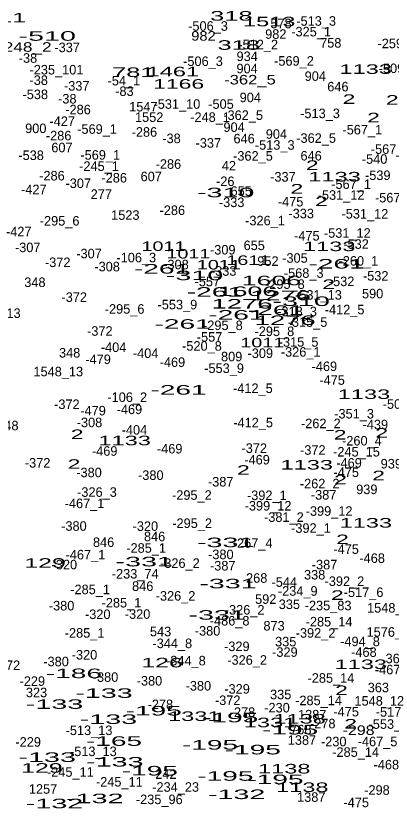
# Model space of a CAD drawing. Extents: x -660434 to -656144, y -997850 to -994016.
# Drawn here: x -658728 to -658570.5, y -995899.8 to -995568.7 of the extents above; entities that cross this region are included whole.
import ezdxf
from ezdxf.enums import TextEntityAlignment as Align

# ---------------------------------------------------------------- set-up
doc = ezdxf.new("R2010")
doc.units = 0
doc.header["$LTSCALE"] = 1.6
doc.layers.add('24', color=7, linetype='Continuous')

msp = doc.modelspace()

# ---------------------------------------------------------------- texts
at = {"layer": '24'}
for s, width, p in [('-411', 1.95, (-658734.082, -995571.44)), ('318', 2, (-658637.537, -995570.7)), ('1513', 1.85, (-658621.664, -995573.09)), ('-510', 2.25, (-658714.797, -995579.13)), ('982', 1.15, (-658649.24, -995579.1)), ('-248_2', 1.35, (-658724.21, -995583.75)), ('318', 2, (-658634.427, -995582.92)), ('781', 2, (-658678.693, -995594.33)), ('1461', 1.85, (-658662.085, -995594.07)), ('1133', 1.85, (-658581.164, -995593.02)), ('-362_5', 1.3, (-658629.73, -995597.47)), ('1166', 1.8, (-658659.663, -995599.24)), ('2', 1.8, (-658588.191, -995605.61)), ('2', 1.8, (-658570.021, -995605.94)), ('2', 1.8, (-658577.881, -995613.36)), ('2', 1.8, (-658603.611, -995633.34)), ('1133', 1.85, (-658594.214, -995638.16)), ('-310', 2.25, (-658639.927, -995644.8)), ('2', 1.8, (-658610.041, -995643.23)), ('2', 1.8, (-658599.771, -995648.51)), ('1011', 1.55, (-658666.026, -995667.31)), ('1133', 1.85, (-658596.484, -995667.38)), ('1011', 1.55, (-658655.566, -995670.48)), ('1611', 1.55, (-658630.425, -995673.19)), ('-261', 2.2, (-658593.385, -995674.69)), ('-261', 2.2, (-658666.635, -995676.8)), ('1011', 1.55, (-658642.796, -995675.09)), ('-310', 2.25, (-658652.977, -995679.57)), ('1606', 2.1, (-658620.713, -995681.72)), ('2', 1.8, (-658596.701, -995683.27)), ('-261', 2.2, (-658644.455, -995686.5)), ('1606', 2.1, (-658630.793, -995686.23)), ('1276', 2.15, (-658616.927, -995688.02)), ('-310', 2.25, (-658608.237, -995690.42)), ('1276', 2.15, (-658633.057, -995691.47)), ('-261', 2.2, (-658618.825, -995694.18)), ('-261', 2.2, (-658635.425, -995696.11)), ('-261', 2.2, (-658657.985, -995699.95)), ('1276', 2.15, (-658614.957, -995698.39)), ('1011', 1.55, (-658624.556, -995707.74)), ('-261', 2.2, (-658659.715, -995727.59)), ('1133', 1.85, (-658581.884, -995729.42)), ('2', 1.8, (-658702.201, -995746.23)), ('2', 1.8, (-658591.891, -995746.42)), ('2', 1.8, (-658574.421, -995745.65)), ('1133', 1.85, (-658682.304, -995748.82)), ('2', 1.8, (-658703.551, -995758.71)), ('1133', 1.85, (-658605.884, -995759)), ('2', 1.8, (-658632.501, -995761.21)), ('2', 1.8, (-658575.761, -995763.51)), ('2', 1.8, (-658591.711, -995765.24)), ('1133', 1.85, (-658581.104, -995783.36)), ('2', 1.8, (-658590.931, -995790.31)), ('-331', 2.25, (-658639.931, -995791.57)), ('129', 1.95, (-658715.713, -995800.22)), ('-331', 2.25, (-658674.111, -995799.64)), ('-331', 2.25, (-658638.971, -995808.86)), ('2', 1.8, (-658593.051, -995813.68)), ('-331', 2.25, (-658643.481, -995822.01)), ('126', 1.95, (-658666.633, -995842.01)), ('1133', 1.85, (-658583.214, -995842.71)), ('-186', 2.2, (-658703.605, -995846.52)), ('2', 1.8, (-658591.321, -995853.63)), ('-133', 2.25, (-658690.991, -995854.79)), ('-133', 2.25, (-658711.731, -995859.4)), ('-195', 2.2, (-658670.115, -995862.19)), ('-133', 2.25, (-658689.121, -995865.74)), ('1331', 1.85, (-658653.094, -995864.48)), ('-195', 2.2, (-658638.035, -995865.07)), ('1138', 1.85, (-658608.914, -995865.57)), ('1331', 1.85, (-658621.294, -995867.12)), ('-195', 2.2, (-658612.885, -995870.16)), ('2', 1.8, (-658587.481, -995867.65)), ('-298', 1.25, (-658584.14, -995870.35)), ('-165', 2.2, (-658686.785, -995874.92)), ('-195', 2.2, (-658646.495, -995876.5)), ('-195', 2.2, (-658628.545, -995878.51)), ('-133', 2.25, (-658714.801, -995881.68)), ('129', 1.95, (-658717.053, -995886.2)), ('-133', 2.25, (-658686.441, -995883.6)), ('1138', 1.85, (-658615.344, -995886.51)), ('-195', 2.2, (-658671.745, -995887.35)), ('-195', 2.2, (-658640.055, -995889.56)), ('-195', 2.2, (-658619.025, -995891)), ('1138', 1.85, (-658607.764, -995894.29)), ('-132', 2.25, (-658694.851, -995898.98)), ('-132', 2.25, (-658635.331, -995897.25)), ('-132', 2.25, (-658711.741, -995901.1))]:
    msp.add_text(s, height=4, dxfattribs=dict(at, width=width)).set_placement(p, align=Align.CENTER)
for s, p in [('-506_3', (-658647.332, -995574.95)), ('578', (-658616.683, -995573.9)), ('-513_3', (-658601.956, -995572.84)), ('982', (-658618.883, -995578.33)), ('-325_1', (-658604.066, -995577.32)), ('758', (-658595.823, -995582.03)), ('-337', (-658706.451, -995583.92)), ('-512_2', (-658626.286, -995582.73)), ('-259_2', (-658567.888, -995582.26)), ('-38', (-658722.885, -995588.37)), ('934', (-658630.897, -995587.66)), ('-506_3', (-658649.442, -995589.73)), ('-569_2', (-658611.263, -995589.6)), ('-235_101', (-658710.933, -995593.28)), ('904', (-658630.921, -995592.8)), ('-509_4', (-658567.366, -995592.7)), ('-38', (-658718.385, -995597.68)), ('-54_1', (-658682.64, -995597.88)), ('904', (-658602.311, -995595.97)), ('-337', (-658702.421, -995600.06)), ('646', (-658592.823, -995600.38)), ('-538', (-658719.825, -995603.62)), ('-83', (-658682.415, -995602.3)), ('904', (-658629.581, -995604.91)), ('-38', (-658706.375, -995605.47)), ('-531_10', (-658660.383, -995607.68)), ('-505', (-658641.879, -995607.69)), ('-286', (-658701.87, -995609.98)), ('1547', (-658674.47, -995608.8)), ('-513_3', (-658600.326, -995611.6)), ('-427', (-658708.515, -995614.89)), ('1552', (-658672.02, -995613.17)), ('-248_1', (-658646.47, -995613.17)), ('-362_5', (-658632.598, -995612.35)), ('900', (-658719.611, -995617.88)), ('-569_1', (-658693.897, -995618.18)), ('904', (-658636.391, -995617.39)), ('-567_1', (-658582.587, -995618.43)), ('-286', (-658710.02, -995620.93)), ('-286', (-658674.03, -995619.4)), ('904', (-658618.631, -995620.27)), ('-38', (-658662.645, -995622.08)), ('-337', (-658647.201, -995624)), ('646', (-658632.183, -995622.18)), ('-513_3', (-658619.336, -995624.85)), ('-362_5', (-658601.978, -995621.96)), ('607', (-658708.622, -995625.92)), ('-567_1', (-658570.687, -995626.59)), ('-538', (-658721.555, -995629.17)), ('-569_1', (-658692.557, -995629.03)), ('-362_5', (-658628.468, -995629.45)), ('646', (-658604.063, -995629.37)), ('-540', (-658577.423, -995630.75)), ('-245_1', (-658693.08, -995633.74)), ('-286', (-658663.95, -995632.85)), ('42', (-658638.561, -995633.56)), ('-286', (-658712.82, -995637.74)), ('607', (-658671.162, -995638.07)), ('-337', (-658615.901, -995638.21)), ('-539', (-658576.1, -995637.57)), ('-307', (-658701.784, -995640.92)), ('-286', (-658686.7, -995638.6)), ('-26', (-658640.08, -995640.09)), ('-567_1', (-658587.297, -995641.29)), ('-427', (-658720.415, -995643.51)), ('655', (-658633.413, -995644.2)), ('277', (-658692.109, -995645.5)), ('-531_12', (-658591.479, -995645.85)), ('-567_1', (-658568.957, -995646.95)), ('-333', (-658637.415, -995648.91)), ('-475', (-658612.675, -995648.65)), ('1523', (-658682.03, -995654.26)), ('-286', (-658662.32, -995652.24)), ('-333', (-658608.225, -995653.61)), ('-531_12', (-658581.489, -995653.72)), ('-295_6', (-658709.603, -995656.67)), ('-326_1', (-658623.422, -995656.58)), ('-427', (-658726.755, -995661.18)), ('-475', (-658605.855, -995662.97)), ('-531_12', (-658588.879, -995661.78)), ('-307', (-658722.994, -995667.82)), ('655', (-658627.943, -995666.96)), ('-532', (-658585.215, -995666.42)), ('-307', (-658697.264, -995670.41)), ('-309', (-658641.144, -995668.81)), ('-372', (-658710.401, -995674.08)), ('-106_3', (-658677.436, -995672.1)), ('952', (-658622.183, -995673.57)), ('-305', (-658610.849, -995672.27)), ('-260_1', (-658584.246, -995673.48)), ('-308', (-658689.669, -995675.87)), ('-308', (-658660.779, -995675.01)), ('-333', (-658640.775, -995677.72)), ('-568_3', (-658607.168, -995678.58)), ('-532', (-658576.965, -995679.77)), ('348', (-658719.981, -995682.45)), ('-557', (-658647.631, -995682.14)), ('-295_8', (-658615.068, -995683.23)), ('-532', (-658591.275, -995682.07)), ('-531_13', (-658600.989, -995687.76)), ('590', (-658578.257, -995687.21)), ('-372', (-658703.481, -995688.68)), ('-295_6', (-658682.333, -995693.65)), ('-553_9', (-658660.188, -995691.82)), ('-412_5', (-658590, -995693.91)), ('1548_13', (-658736.376, -995695.42)), ('-318_3', (-658609.956, -995694.71)), ('-295_8', (-658641.088, -995700.51)), ('-315_5', (-658605.586, -995699.14)), ('-372', (-658692.731, -995702.89)), ('-295_8', (-658619.488, -995703.02)), ('-557', (-658646.681, -995705.38)), ('-315_5', (-658609.326, -995707.49)), ('-404', (-658686.957, -995709.71)), ('-520_8', (-658649.876, -995709.16)), ('348', (-658705.391, -995712.03)), ('-404', (-658673.517, -995712.21)), ('809', (-658637.417, -995713.61)), ('-309', (-658625.404, -995712.22)), ('-326_1', (-658608.442, -995711.67)), ('-479', (-658693.46, -995714.78)), ('-469', (-658662.269, -995715.97)), ('-469', (-658598.519, -995717.7)), ('1548_13', (-658710.166, -995719.91)), ('-553_9', (-658640.598, -995718.51)), ('-475', (-658595.255, -995723.46)), ('-412_5', (-658628.5, -995726.91)), ('-106_2', (-658681.236, -995730.66)), ('-372', (-658706.561, -995733.63)), ('-503', (-658568.659, -995733.53)), ('-479', (-658695.57, -995736.3)), ('-469', (-658680.319, -995735.76)), ('-351_3', (-658586.046, -995737.6)), ('348', (-658731.311, -995742.57)), ('-308', (-658697.069, -995741.24)), ('-412_5', (-658628.4, -995741.32)), ('-262_2', (-658599.988, -995741.66)), ('-439', (-658577.115, -995742.13)), ('-404', (-658678.217, -995744.38)), ('-260_4', (-658582.756, -995748.93)), ('-469', (-658690.689, -995753.23)), ('-469', (-658663.419, -995752.27)), ('-372', (-658627.931, -995752.04)), ('-372', (-658603.351, -995752.81)), ('-245_15', (-658585.029, -995753.55)), ('-469', (-658626.749, -995756.88)), ('-372', (-658718.841, -995758.21)), ('-469', (-658588.159, -995758.23)), ('939', (-658570.418, -995758.57)), ('-380', (-658697.259, -995762.23)), ('-380', (-658671.339, -995763.38)), ('-475', (-658589.335, -995762.15)), ('-387', (-658642.011, -995766.13)), ('-262_2', (-658600.468, -995766.92)), ('-326_3', (-658693.938, -995770.46)), ('939', (-658580.688, -995769.32)), ('-295_2', (-658654.098, -995771.72)), ('-392_1', (-658622.662, -995771.83)), ('-387', (-658598.811, -995771.6)), ('-467_1', (-658699.152, -995775.21)), ('-399_12', (-658622.146, -995776.21)), ('-399_12', (-658596.516, -995778.42)), ('-295_2', (-658653.998, -995783.53)), ('-381_2', (-658615.496, -995780.96)), ('-380', (-658703.599, -995784.7)), ('-320', (-658673.629, -995784.76)), ('-392_1', (-658604.132, -995785.56)), ('846', (-658669.747, -995789.09)), ('846', (-658691.147, -995791.49)), ('-285_1', (-658673.296, -995793.92)), ('-267_4', (-658628.598, -995791.85)), ('-467_1', (-658698.772, -995796.71)), ('-380', (-658641.959, -995796.61)), ('-475', (-658589.365, -995794.39)), ('-326_2', (-658659.138, -995800.28)), ('-468', (-658578.455, -995798.18)), ('-320', (-658707.619, -995800.89)), ('-387', (-658641.151, -995801.36)), ('-387', (-658598.431, -995800.89)), ('-233_74', (-658677.891, -995804.75)), ('268', (-658626.893, -995806.52)), ('338', (-658602.587, -995805.14)), ('846', (-658674.737, -995809.93)), ('-544', (-658615.323, -995808.21)), ('-392_2', (-658590.098, -995807.85)), ('-285_1', (-658696.816, -995811.3)), ('-234_9', (-658609.682, -995811.95)), ('-517_6', (-658582.047, -995812.49)), ('-285_1', (-658683.666, -995816.88)), ('-326_2', (-658660.958, -995814.01)), ('592', (-658623.113, -995815.36)), ('-380', (-658708.779, -995818.12)), ('-326_2', (-658631.968, -995819.87)), ('335', (-658613.187, -995817.54)), ('-235_83', (-658596.941, -995818.06)), ('1548_12', (-658570.186, -995819.02)), ('-320', (-658693.599, -995821.73)), ('-320', (-658676.899, -995821.64)), ('-486_8', (-658638.262, -995824.44)), ('873', (-658619.623, -995826.54)), ('-285_14', (-658596.529, -995824.83)), ('-285_1', (-658699.126, -995829.55)), ('543', (-658667.241, -995828.95)), ('-380', (-658647.529, -995828.69)), ('-392_2', (-658602.208, -995829.56)), ('1576_3', (-658571.88, -995829.14)), ('335', (-658614.727, -995833.2)), ('-494_8', (-658583.546, -995833.12)), ('-344_8', (-658662.321, -995833.93)), ('-329', (-658635.24, -995835.18)), ('-320', (-658699.169, -995838.72)), ('-329', (-658615.08, -995837.58)), ('-468', (-658581.915, -995837.6)), ('363', (-658568.363, -995840.26)), ('-372', (-658731.521, -995843.11)), ('-380', (-658711.089, -995841.56)), ('-344_8', (-658656.611, -995841.18)), ('-326_2', (-658630.918, -995840.9)), ('-467_5', (-658568.988, -995844.93)), ('-229', (-658721.07, -995849.77)), ('-380', (-658690.349, -995848.08)), ('-380', (-658671.909, -995849.62)), ('-285_14', (-658595.759, -995848.46)), ('-380', (-658651.369, -995851.74)), ('-329', (-658635.14, -995853.05)), ('363', (-658575.853, -995852.46)), ('323', (-658719.287, -995854.52)), ('335', (-658616.837, -995855.38)), ('-278', (-658667.331, -995859.53)), ('-372', (-658639.071, -995857.8)), ('-285_14', (-658600.949, -995857.87)), ('1548_12', (-658575.456, -995858.07)), ('-278', (-658632.871, -995862.79)), ('-230', (-658618.379, -995860.92)), ('-475', (-658589.365, -995862.58)), ('-517_6', (-658568.607, -995862.67)), ('1387', (-658603.596, -995863.84)), ('768', (-658608.368, -995870.08)), ('-278', (-658599.181, -995867.58)), ('-553_14', (-658570.149, -995867.79)), ('-513_13', (-658697.269, -995870.4)), ('-229', (-658722.8, -995875.29)), ('1387', (-658607.916, -995874.49)), ('-230', (-658594.569, -995875.13)), ('-467_5', (-658576.198, -995875.11)), ('-513_13', (-658695.449, -995879.23)), ('-285_14', (-658585.389, -995879.54)), ('-468', (-658572.505, -995884.8)), ('-245_11', (-658705.093, -995887.89)), ('-242', (-658665.899, -995888.77)), ('-245_11', (-658684.543, -995892.02)), ('1257', (-658716.556, -995895.02)), ('-234_23', (-658660.916, -995894.19)), ('-298', (-658576.43, -995895.46)), ('-235_96', (-658667.782, -995899.38)), ('1387', (-658603.986, -995898.41)), ('-475', (-658585.145, -995900.66))]:
    msp.add_text(s, height=4, dxfattribs=at).set_placement(p, align=Align.CENTER)

doc.saveas('drawing.dxf')
